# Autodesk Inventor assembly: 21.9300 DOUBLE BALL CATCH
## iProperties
Created: 2010-11
Part Number: 21.9300 DOUBLE BALL CATCH
Document SubType Name: Assembly
Designer: Administrator
Author: Administrator
